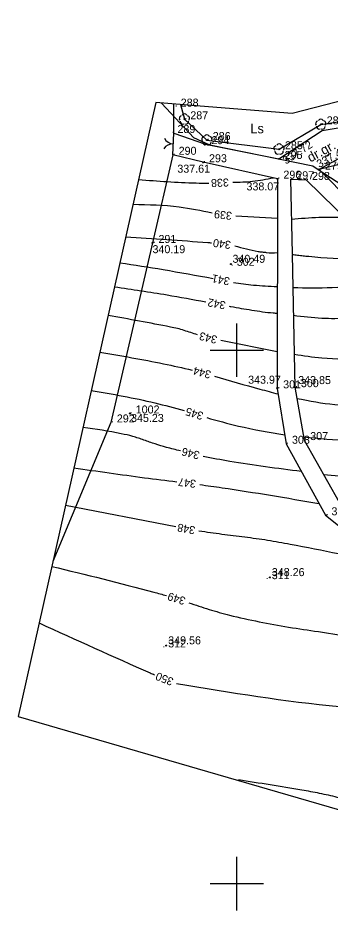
# Model space of a CAD drawing. Extents: x 4632591 to 4653165, y 5351032 to 5369868.
# Drawn here: x 4644559 to 4644617.6, y 5358293.2 to 5358462.3 of the extents above; entities that cross this region are included whole.
import ezdxf

# ---------------------------------------------------------------- set-up
doc = ezdxf.new("R2010")
doc.units = 0
for name, color, linetype in [('EKLPK_217', 7, 'Continuous'), ('EUZPU_424', 7, 'Continuous'), ('SZOPO_902', 7, 'Continuous'), ('SZOPO_905', 7, 'Continuous'), ('SZZPZ_922', 7, 'Continuous'), ('UEEPO_585', 7, 'Continuous'), ('Warstwa 40', 7, 'Continuous'), ('Warstwa 60', 7, 'Continuous'), ('Warstwa 62', 7, 'Continuous'), ('WUKPS_403', 7, 'Continuous'), ('WUKPS_823', 7, 'Continuous'), ('WWRPH_811', 7, 'Continuous')]:
    doc.layers.add(name, color=color, linetype=linetype)

msp = doc.modelspace()

# ---------------------------------------------------------------- linework, layer by layer
at = {"layer": 'EKLPK_217'}
msp.add_lwpolyline([(4644589.44, 5358446.06), (4644590.15, 5358443.3), (4644594.36, 5358439.41), (4644607.9, 5358437.69), (4644615.73, 5358442.35), (4644623.29, 5358443.5), (4644627.91, 5358442.78), (4644641.76, 5358446.85), (4644656.67, 5358456.98), (4644668.51, 5358469.17), (4644674.28, 5358475.79), (4644680.61, 5358483.06), (4644678.25, 5358495.41), (4644671.51, 5358518.45)], dxfattribs=at)
at = {"layer": 'EUZPU_424'}
for p, q in [((4644615.41, 5358433.87), (4644622.58, 5358426.64)), ((4644610.03, 5358432.06), (4644612.98, 5358431.93))]:
    msp.add_line(p, q, dxfattribs=at)
for points in [[(4644588.18, 5358440.71), (4644594.11, 5358438.64), (4644607.85, 5358435.87), (4644616, 5358441.22), (4644623.54, 5358442.48), (4644628.11, 5358442), (4644642.18, 5358446.34), (4644645.62, 5358448.34)], [(4644643, 5358444.41), (4644625.77, 5358438.44), (4644620.64, 5358436.74), (4644615.41, 5358433.87)], [(4644607.61, 5358432.17), (4644593.66, 5358435.25), (4644587.96, 5358436.65)], [(4644607.61, 5358432.17), (4644607.56, 5358392.86), (4644609.22, 5358382.47), (4644616.62, 5358369.06), (4644630.54, 5358357.95), (4644642.13, 5358351.82), (4644658.62, 5358347.91), (4644680.81, 5358342.06)], [(4644610.03, 5358432.06), (4644610.34, 5358418.06)], [(4644612.98, 5358431.93), (4644621.22, 5358423.87), (4644623.01, 5358422.57)], [(4644610.34, 5358417.96), (4644610.89, 5358393.08), (4644612.64, 5358383.16), (4644619.15, 5358371.52), (4644632.13, 5358360.72), (4644643.74, 5358354.36), (4644681.29, 5358345.24)]]:
    msp.add_lwpolyline(points, dxfattribs=at)
at = {"layer": 'SZOPO_902'}
for p, q in [((4644588.18, 5358440.71), (4644588.2, 5358446.16)), ((4644587.96, 5358436.65), (4644588.18, 5358440.71))]:
    msp.add_line(p, q, dxfattribs=at)
msp.add_lwpolyline([(4644587.96, 5358436.65), (4644584.18, 5358420.11), (4644576.37, 5358386.47), (4644565.48, 5358360.4)], dxfattribs=at)
at = {"layer": 'SZOPO_905'}
for centre, start, end in [((4644588.18, 5358440.68), 206.871, 266.871), ((4644587.96, 5358436.68), 86.871, 146.871)]:
    msp.add_arc(centre, 2, start, end, dxfattribs=at)
at = {"layer": 'SZZPZ_922'}
for centre in [(4644590.15, 5358443.3), (4644615.73, 5358442.35), (4644594.36, 5358439.41), (4644607.9, 5358437.69)]:
    msp.add_circle(centre, 0.09, dxfattribs=at)
for centre, start, end in [((4644589.68, 5358443.45), 103.0519, 221.3352), ((4644589.86, 5358442.9), 174.1727, 292.6157), ((4644590.16, 5358443.8), 30.7696, 149.2306), ((4644590.45, 5358442.89), 246.131, 4.5225), ((4644590.63, 5358443.46), 318.939, 77.5551), ((4644615.26, 5358442.5), 103.0519, 221.3352), ((4644615.74, 5358442.85), 30.7696, 149.2306), ((4644616.21, 5358442.51), 318.939, 77.5551), ((4644615.44, 5358441.95), 174.1727, 292.6157), ((4644616.03, 5358441.94), 246.131, 4.5225), ((4644593.89, 5358439.56), 103.0519, 221.3352), ((4644594.37, 5358439.91), 30.7696, 149.2306), ((4644594.84, 5358439.57), 318.939, 77.5551), ((4644594.07, 5358439.01), 174.1727, 292.6157), ((4644594.66, 5358439), 246.131, 4.5225), ((4644607.43, 5358437.84), 103.0519, 221.3352), ((4644607.91, 5358438.19), 30.7696, 149.2306), ((4644608.38, 5358437.85), 318.939, 77.5551), ((4644607.61, 5358437.29), 174.1727, 292.6157), ((4644608.2, 5358437.28), 246.131, 4.5225)]:
    msp.add_arc(centre, 0.5, start, end, dxfattribs=at)
at = {"layer": 'UEEPO_585'}
msp.add_lwpolyline([(4644654.76, 5358408.32), (4644637.89, 5358419.2), (4644615.63, 5358433.57), (4644614.21, 5358434.49), (4644594.95, 5358438.48), (4644591.95, 5358439.84), (4644585.88, 5358446.34)], dxfattribs=at)
at = {"layer": 'Warstwa 40'}
msp.add_lwpolyline([(4644810.83, 5358555.03), (4644734.32, 5358627.59), (4644688.9, 5358576.34), (4644696.21, 5358541.05), (4644665.65, 5358513.08), (4644675.21, 5358482.87), (4644634.26, 5358446.15), (4644624.66, 5358448.08), (4644610.34, 5358444.41), (4644593.08, 5358445.77), (4644584.82, 5358446.42), (4644558.95, 5358331.35), (4644690.29, 5358293.2), (4644705.73, 5358386.52), (4644692.29, 5358404.57), (4644776.59, 5358522.67)], close=True, dxfattribs=at)
at = {"layer": 'Warstwa 60'}
for p, q in [((4644600, 5358395), (4644600, 5358405)), ((4644595, 5358400), (4644605, 5358400)), ((4644600, 5358295), (4644600, 5358305)), ((4644595, 5358300), (4644605, 5358300))]:
    msp.add_line(p, q, dxfattribs=at)
at = {"layer": 'WUKPS_403'}
for centre in [(4644607.91, 5358435.88), (4644593.66, 5358435.23), (4644615.45, 5358433.9), (4644607.61, 5358432.13), (4644584.17, 5358420.13), (4644598.87, 5358416.15), (4644607.53, 5358392.89), (4644607.54, 5358392.88), (4644610.94, 5358393.05), (4644579.91, 5358388.15), (4644606.19, 5358357.42), (4644586.76, 5358344.63)]:
    msp.add_circle(centre, 0.09, dxfattribs=at)
at = {"layer": 'WUKPS_823'}
msp.add_lwpolyline([(4644677.51, 5358471.74), (4644659.55, 5358453.11), (4644654.2, 5358447.6), (4644648.52, 5358444.01), (4644643.29, 5358441.85), (4644629.93, 5358437.54), (4644615.41, 5358433.87)], dxfattribs=at)
at = {"layer": 'WWRPH_811'}
for p, q in [((4644607.6, 5358424.68), (4644599.81, 5358425.17)), ((4644607.57, 5358399.72), (4644596.98, 5358401.81)), ((4644588.55, 5358366.87), (4644567.83, 5358370.87))]:
    msp.add_line(p, q, dxfattribs=at)
for points in [[(4644581.58, 5358432.01), (4644592.33, 5358431.37), (4644594.71, 5358431.33)], [(4644599.24, 5358431.49), (4644602.93, 5358431.68), (4644606.85, 5358432.33)], [(4644595.35, 5358425.7), (4644589.15, 5358426.83), (4644580.52, 5358427.31)], [(4644620.2, 5358424.87), (4644615.36, 5358424.87), (4644610.2, 5358424.53)], [(4644579.16, 5358421.26), (4644594.56, 5358420.2), (4644595.21, 5358420.15)], [(4644599.59, 5358419.59), (4644603.98, 5358418.52), (4644604.29, 5358418.47), (4644604.6, 5358418.44), (4644604.91, 5358418.42), (4644605.22, 5358418.39), (4644605.3, 5358418.38), (4644605.38, 5358418.37), (4644605.54, 5358418.34), (4644607.59, 5358418.3)], [(4644610.34, 5358417.96), (4644611.38, 5358417.83), (4644611.9, 5358417.77), (4644612.43, 5358417.72), (4644613.48, 5358417.62), (4644622.65, 5358416.97)], [(4644578.07, 5358416.41), (4644586.17, 5358415.13), (4644595.54, 5358413.46)], [(4644599.36, 5358412.73), (4644603.09, 5358412.23), (4644607.58, 5358411.96)], [(4644610.48, 5358411.77), (4644617.86, 5358411.77), (4644626.47, 5358412.54), (4644629.31, 5358412.83), (4644636.99, 5358413.44)], [(4644577.06, 5358411.9), (4644586.9, 5358410.39), (4644594.17, 5358409.08)], [(4644598.58, 5358408.26), (4644598.85, 5358408.21), (4644600.83, 5358407.86), (4644602.82, 5358407.53), (4644604.81, 5358407.23), (4644606.81, 5358407.01), (4644607.58, 5358406.94)], [(4644610.59, 5358406.56), (4644615.93, 5358406.03), (4644620.83, 5358406.03), (4644627.41, 5358406.44), (4644633.08, 5358407.3), (4644639.7, 5358407.77), (4644646.06, 5358407.62)], [(4644592.62, 5358402.9), (4644591.36, 5358403.31), (4644590.1, 5358403.71), (4644588.84, 5358404.08), (4644587.55, 5358404.36), (4644575.85, 5358406.52)], [(4644574.3, 5358399.64), (4644586.25, 5358397.46), (4644591.58, 5358396.29)], [(4644661.33, 5358397.54), (4644644.59, 5358397.54), (4644623.91, 5358398.16), (4644615.92, 5358398.52), (4644610.76, 5358399.18)], [(4644595.81, 5358395.15), (4644604.32, 5358392.72), (4644607.73, 5358391.81)], [(4644572.69, 5358392.47), (4644584.61, 5358390.14), (4644590.09, 5358388.71)], [(4644611.26, 5358390.98), (4644618.34, 5358389.86), (4644626.91, 5358389.86), (4644651.61, 5358388.73), (4644674.42, 5358388.66)], [(4644594.33, 5358387.37), (4644600.29, 5358385.8), (4644608.96, 5358384.12)], [(4644589.42, 5358381.13), (4644586.79, 5358381.79), (4644584.67, 5358382.43), (4644582.57, 5358383.16), (4644580.46, 5358383.85), (4644578.31, 5358384.35), (4644571.13, 5358385.54)], [(4644612.53, 5358383.78), (4644621.18, 5358383.11), (4644630.98, 5358383.3), (4644655.19, 5358382.61), (4644665.45, 5358381.95), (4644684.42, 5358381.35)], [(4644612.09, 5358377.28), (4644598.65, 5358379.16), (4644593.67, 5358380.09)], [(4644569.43, 5358377.97), (4644582.65, 5358376.11), (4644588.76, 5358375.34)], [(4644647.83, 5358374.86), (4644637.8, 5358375.83), (4644621.98, 5358376.21), (4644616.28, 5358376.66)], [(4644593.05, 5358374.82), (4644597.21, 5358374.23), (4644615.39, 5358371.28)], [(4644628.1, 5358359.9), (4644610.01, 5358363.6), (4644605.75, 5358364.35), (4644601.47, 5358364.95), (4644597.18, 5358365.49), (4644592.89, 5358366.09)], [(4644565.27, 5358359.47), (4644584.4, 5358354.66), (4644586.79, 5358354)], [(4644590.97, 5358352.67), (4644594.78, 5358351.43), (4644596.7, 5358350.86), (4644598.64, 5358350.34), (4644604.16, 5358349.11), (4644609.7, 5358348.09), (4644615.28, 5358347.26), (4644639.83, 5358342.45)], [(4644562.89, 5358348.88), (4644583.75, 5358339.5), (4644584.52, 5358339.16)], [(4644588.68, 5358337.51), (4644619.23, 5358333.21), (4644652.1, 5358331.74)], [(4644651.42, 5358311.17), (4644649.6, 5358311.34), (4644646.87, 5358311.4), (4644644.13, 5358311.25), (4644641.4, 5358311.14), (4644640.04, 5358311.18), (4644638.69, 5358311.34), (4644632.03, 5358312.74), (4644625.43, 5358314.46), (4644618.83, 5358316.18), (4644615.51, 5358316.92), (4644612.17, 5358317.54), (4644600.28, 5358319.44)]]:
    msp.add_spline(points, degree=3, dxfattribs=at)

# ---------------------------------------------------------------- texts
at = {"layer": 'EKLPK_217'}
msp.add_text('Ls', height=1.8, dxfattribs=at).set_placement((4644602.52, 5358440.67))
at = {"layer": 'EUZPU_424'}
msp.add_text('dr.gr.', height=1.8, rotation=28.7561, dxfattribs=at).set_placement((4644613.8, 5358435.18))
at = {"layer": 'Warstwa 62'}
for s, p in [('. 288', (4644588.35, 5358445.68)), ('. 287', (4644590.15, 5358443.3)), ('. 284', (4644615.73, 5358442.35)), ('. 289', (4644587.74, 5358440.73)), ('. 294', (4644594.11, 5358438.64)), ('. 286', (4644594.36, 5358439.41)), ('. 290', (4644587.96, 5358436.65)), ('. 285', (4644607.9, 5358437.69)), ('. 293', (4644593.66, 5358435.25)), ('. 295', (4644607.85, 5358435.87)), ('. 279', (4644615.41, 5358433.87)), ('. 296', (4644607.61, 5358432.17)), ('. 297', (4644610.03, 5358432.06)), ('. 298', (4644612.98, 5358431.93)), ('. 291', (4644584.18, 5358420.11)), ('. 302', (4644598.86, 5358415.84)), ('. 301', (4644607.56, 5358392.86)), ('. 300', (4644610.89, 5358393.08)), ('. 1002', (4644579.91, 5358388.15)), ('. 1002', (4644579.91, 5358388.15)), ('. 1002', (4644579.91, 5358388.15)), ('. 1002', (4644579.91, 5358388.15)), ('. 292', (4644576.37, 5358386.47)), ('. 308', (4644609.22, 5358382.47)), ('. 307', (4644612.64, 5358383.16)), ('. 310', (4644616.62, 5358369.06)), ('. 311', (4644605.42, 5358357.09)), ('. 312', (4644585.99, 5358344.29))]:
    msp.add_text(s, height=1.5, dxfattribs=at).set_placement(p)
at = {"layer": 'WUKPS_403'}
for s, rotation, p in [('337.72', 33.2773, (4644609.2, 5358434.79)), ('337.46', 28.7561, (4644615.47, 5358434.15))]:
    msp.add_text(s, height=1.5, rotation=rotation, dxfattribs=at).set_placement(p)
for s, p in [('337.61', (4644588.83, 5358433.29)), ('338.07', (4644601.8, 5358429.97)), ('340.19', (4644584.17, 5358418.2)), ('340.49', (4644599.17, 5358416.4)), ('343.97', (4644602.11, 5358393.73)), ('343.85', (4644611.5, 5358393.66)), ('345.23', (4644580.15, 5358386.56)), ('348.26', (4644606.55, 5358357.66)), ('349.56', (4644587.12, 5358344.87))]:
    msp.add_text(s, height=1.5, dxfattribs=at).set_placement(p)
at = {"layer": 'WWRPH_811'}
for s, rotation, p in [('338', 182.4777, (4644598.46, 5358432.22)), ('339', 173.6595, (4644599.14, 5358425.91)), ('340', 172.4678, (4644598.95, 5358420.45)), ('341', 168.9549, (4644598.77, 5358413.61)), ('342', 169.373, (4644597.98, 5358409.12)), ('343', 166.089, (4644596.42, 5358402.64)), ('344', 164.8513, (4644595.28, 5358396.08)), ('345', 162.347, (4644593.84, 5358388.31)), ('346', 166.2761, (4644593.12, 5358380.98)), ('347', 173.1489, (4644592.4, 5358375.67)), ('348', 169.7876, (4644592.28, 5358366.94)), ('349', 162.2234, (4644590.49, 5358353.63)), ('350', 158.3233, (4644588.25, 5358338.45))]:
    msp.add_text(s, height=1.5, rotation=rotation, dxfattribs=at).set_placement(p)

doc.saveas('drawing.dxf')
